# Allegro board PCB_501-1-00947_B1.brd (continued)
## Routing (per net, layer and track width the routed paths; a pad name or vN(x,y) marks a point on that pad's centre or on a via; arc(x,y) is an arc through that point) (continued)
SD2_DATA1: length 90.5
  TOP w0.137: v1(101.19,15.88) R179.1
  L3_INT_1 w0.127: v1(58.03,71.01) 58,70.99 57.31,70.99 57.12,70.79 57.12,69.69 57.37,69.44 57.61,69.44 57.82,69.23 57.82,60.83 63.37,55.28 63.37,54.86 79.98,38.25 79.98,24.24 88.35,15.88 89.6,15.88 89.79,15.69 89.79,15.5 89.97,15.32 90.24,15.32 90.42,15.5 90.42,15.79 90.58,15.95 90.84,15.95 91.06,15.74 91.06,15.5 91.24,15.32 91.51,15.32 91.69,15.5 91.69,15.79 91.85,15.95 92.11,15.95 92.33,15.74 92.33,15.5 92.51,15.32 92.78,15.32 92.96,15.5 92.96,15.79 93.12,15.95 93.38,15.95 93.6,15.74 93.6,15.5 93.78,15.32 94.05,15.32 94.23,15.5 94.23,15.79 94.39,15.95 94.65,15.95 94.87,15.74 94.87,15.5 95.05,15.32 95.32,15.32 95.5,15.5 95.5,15.79 95.66,15.95 95.92,15.95 96.14,15.74 96.14,15.5 96.32,15.32 96.59,15.32 96.77,15.5 96.77,15.79 96.93,15.95 97.19,15.95 97.41,15.74 97.41,15.5 97.59,15.32 97.86,15.32 98.12,15.58 98.53,15.58 98.8,15.32 99.13,15.32 99.31,15.5 99.31,15.69 99.5,15.88 99.76,15.88 99.95,15.69 99.95,15.5 100.13,15.32 100.4,15.32 100.58,15.5 100.58,15.69 100.77,15.88 v1(101.19,15.88)
  BOTTOM w0.137: R289.1 58.04,71.01 v1(58.03,71.01) ; R179.1 v1(101.19,15.88)
SD2_DATA2: length 88
  TOP w0.137: v1(101.19,14.73) R180.1
  L3_INT_1 w0.127: v1(57.2,68.8) 57.2,60.62 62.78,55.04 62.78,54.45 78.96,38.27 78.96,24.25 88.48,14.73 89.52,14.73 89.71,14.55 89.71,14.36 89.89,14.17 90.16,14.17 90.34,14.36 90.34,14.55 90.53,14.73 90.79,14.73 90.98,14.55 90.98,14.36 91.16,14.17 91.43,14.17 91.61,14.36 91.61,14.55 91.8,14.73 92.06,14.73 92.25,14.55 92.25,14.36 92.43,14.17 92.7,14.17 92.88,14.36 92.88,14.55 93.07,14.73 93.33,14.73 93.52,14.55 93.52,14.36 93.7,14.17 93.97,14.17 94.15,14.36 94.15,14.53 94.3,14.68 101.14,14.68 v1(101.19,14.73)
  BOTTOM w0.137: v1(57.2,68.8) 58.01,67.99 58.37,67.99 R290.1 ; R180.1 v1(101.19,14.73)
SD2_DATA3: length 95.5
  TOP w0.137: v1(101.19,13.59) R181.1
  L3_INT_1 w0.127: v1(101.19,13.59) 100.99,13.78 97.04,13.78 96.81,13.55 88.56,13.55 77.94,24.17 77.94,38.22 56.39,59.78 56.39,62.81 56.2,63 54.29,63 54.11,63.18 54.11,63.45 54.29,63.63 56.2,63.63 56.39,63.82 56.39,64.08 56.2,64.27 54.29,64.27 54.11,64.45 54.11,64.72 54.29,64.9 56.2,64.9 56.39,65.09 56.39,71.94 v1(56.69,72.24)
  BOTTOM w0.137: R291.1 56.69,72.71 v1(56.69,72.24) ; R181.1 v1(101.19,13.59)
SD3_CLK: length 8
  TOP w0.137: R125.1 65.72,63.73 65.72,69.93 R444.1
SD3_CLK_R: length 10.4
  TOP w0.076: 69.5,57.08 69.73,57.31 69.73,57.54 69.59,57.68 69.59,57.88 69.73,58.02 69.73,58.23 69.49,58.48 U10.M6
  TOP w0.137: 69.5,57.08 69.1,56.68 68.6,56.68 64.01,61.26 R125.2
SD3_CMD: length 15.3
  TOP w0.076: 67,62.39 69.51,59.88 69.51,59.57 U10.M5
  TOP w0.137: R445.1 67.34,71.46 67.8,71 67.8,70.15 66.18,68.53 66.18,68.28 R94.2 ; 66.45,68.01 R94.2 ; R94.2 66.45,62.94 67,62.39
SD3_DATA0: length 14.5
  TOP w0.076: 72.51,64.3 72.51,63.98 U10.A3
  TOP w0.137: v1(64.53,68.17) 64.53,68.57 R436.1 ; v1(71.7,65.54) 71.46,65.54 71.16,65.84 71.16,66.14 71.44,66.42 71.67,66.42 72.33,65.76 72.33,65.56 72.19,65.41 72.19,64.97 72.51,64.64 72.51,64.3
  L3_INT_1 w0.127: v1(64.53,68.17) 64.53,67.89 67.31,65.11 71.28,65.11 v1(71.7,65.54)
SD3_DATA1: length 13.4
  TOP w0.076: 72.81,64.3 72.81,63.58 72.67,63.44
  TOP w0.137: 72.81,64.3 72.81,65.05 v1(72.64,65.23) ; R437.1 64.03,67.78 v1(64.03,67.46)
  L3_INT_1 w0.127: v1(64.03,67.46) 66.95,64.53 67.06,64.53 67.06,64.53 71.52,64.53 71.52,64.53 72.51,64.53 72.64,64.66 v1(72.64,65.23)
SD3_DATA2: length 17
  TOP w0.076: U10.A5 73.44,63.5 73.44,63.68
  TOP w0.137: 73.44,63.68 73.44,64.81 74.12,65.49 74.12,67.13 73.92,67.32 73.73,67.32 73.4,66.99 73.21,66.99 73.01,67.19 73.01,67.38 73.37,67.73 73.37,67.93 73.17,68.12 71.54,68.12 71.21,67.79 v1(70.91,67.79) ; v1(69.73,73.37) 69.73,73.61 69.29,74.05
  L3_INT_1 w0.127: v1(69.73,73.37) 71.62,71.48 71.62,68.51 70.91,67.79 v1(70.91,67.79)
SD3_DATA3: length 16.2
  TOP w0.076: 70.7,65.05 70.45,65.05
  TOP w0.081: U10.B2 71.61,64.14 70.7,65.05
  TOP w0.137: R438.1 68.99,73.1 v1(68.99,72.68) ; v1(70.15,67.92) 70.15,67.92 70.15,67.21 69.59,66.65 69.59,66.34 69.72,66.22 70.02,66.22 70.17,66.07 70.17,65.79 70.02,65.63 69.46,65.63 69.11,65.98 68.92,65.98 68.65,65.71 68.65,64.54 68.85,64.34 69.18,64.34 69.33,64.49 69.33,64.87 69.51,65.05 70.45,65.05
  L3_INT_1 w0.127: v1(70.15,67.92) 70.15,70.29 70.13,70.3 70.13,71.54 v1(68.99,72.68)
SD3_DATA4: length 16.7
  TOP w0.081: 70.5,64.54 71.61,63.44 U10.B3
  TOP w0.137: v1(69.64,67.46) 68.24,66.07 68.24,63.88 68.42,63.7 68.78,63.7 68.97,63.51 68.97,63.16 69.16,62.97 69.44,62.97 69.91,63.44 69.91,63.61 69.6,63.92 69.6,64.15 69.99,64.54 70.5,64.54 ; v1(68.39,71.99) 68.39,72.39 R440.1
  L3_INT_1 w0.127: v1(69.64,67.46) 69.11,67.46 68.39,68.19 v1(68.39,71.99)
SD3_DATA5: length 18.3
  TOP w0.076: U10.B4 72.32,63.44
  TOP w0.081: 72.23,64.34 72.23,64.05 72.05,63.87 72.05,63.71 72.32,63.44
  TOP w0.137: v1(67,70.67) 67,71.17 R441.1 ; v1(70.62,67.17) 70.62,65.69 71.25,65.06 71.51,65.06 72.23,64.34
  L3_INT_1 w0.127: v1(67,70.67) 66.57,71.09 66.16,71.09 65.8,70.74 65.42,70.74 65.19,70.97 65.19,71.27 66,72.08 66.6,72.08 67.43,71.24 67.43,68.27 68.83,66.88 70.33,66.88 v1(70.62,67.17)
SD3_DATA6: length 16.3
  TOP w0.076: 73.12,63.54 73.12,63.89
  TOP w0.081: 73.12,63.54 72.67,63.08 U10.B5
  TOP w0.137: 73.12,63.89 73.12,65.38 73.63,65.89 73.63,66.17 73.4,66.4 73.12,66.4 72.89,66.17 72.64,66.17 72.28,66.52 72.28,67.39 72.1,67.56 71.7,67.56 v1(71.29,67.16) ; R443.1 66.72,70.18 v1(66.72,69.72)
  L3_INT_1 w0.127: v1(71.29,67.16) 71.2,67.07 71.2,66.93 70.57,66.3 68.58,66.3 66.76,68.12 66.76,69.68 v1(66.72,69.72)
SD3_DATA7: length 18.9
  TOP w0.076: 73.66,63.37 73.7,63.41
  TOP w0.081: 73.66,63.37 73.02,62.73 U10.B6
  TOP w0.127: 73.7,63.41 73.79,63.49
  TOP w0.137: 73.79,63.49 73.79,64.37 v1(73.95,64.54) ; R442.1 65.18,69.21 v1(65.18,68.33)
  L3_INT_1 w0.127: v1(73.95,64.54) 73.95,65.69 73.4,66.25 71.52,66.25 70.97,65.7 68.35,65.7 66.13,67.91 66.13,69.07 65.26,69.94 65.08,69.94 64.67,69.53 64.67,68.83 v1(65.18,68.33)
SD3_RESET_B: length 17.2
  TOP w0.076: U10.K5 69.84,60.76 69.8,60.8 69.8,61 67.71,63.09
  TOP w0.137: R446.1 70.19,74.43 70.19,72.61 68.2,70.62 R93.2 68.2,67.3 67.23,66.32 67.23,63.58 67.71,63.09
SD3_STROBE: length 9
  TOP w0.137: v1(68.95,68.26) 68.93,68.28 68.93,68.35 68.56,68.72 68.56,70.14 70.56,72.14 R447.1
  BOTTOM w0.137: R124.1 68.81,67.41 68.95,67.55 v1(68.95,68.26)
SD3_STROBE_R: length 9.7
  TOP w0.137: v1(70.2,60.96) 70.55,60.61 U10.H5
  BOTTOM w0.137: R124.2 66.85,64.49 66.85,62.62 68.52,60.95 R691.2 69.82,60.58 v1(70.2,60.96)
SD_PWR_CTRL: length 4.7
  BOTTOM w0.254: C194.2 92.47,54.25 R107.1
  BOTTOM w0.381: R107.1 93.67,54.2 Q6.1 93.67,55.04 R105.2
SD_PWR_DISCH: length 4.2
  BOTTOM w0.254: Q7.1 96.33,57.92 R104.2 96.99,56.64 98.26,55.37 D4.2
SOC_OTG2_DN: length 8.1
  TOP w0.127: 53.8,73.26 53.45,73.26 53.34,73.15 53.15,73.15 53.03,73.28 53.03,73.45 54.85,75.28 R559.1 55.82,75.53 55.82,75.79 55.38,76.23 55.38,77.68 56.05,78.34 U7.A10
SOC_OTG2_DP: length 8.8
  TOP w0.127: U7.B10 56.19,78.87 55.11,77.79 55.11,76.32 54.99,76.19 R558.1 54.55,75.36 52.75,73.57 52.75,73.04 52.9,72.89 R565.1
SOC_SD1_CLK: length 4.9
  TOP w0.137: R49.2 57.7,72.82 57.7,74.88 58.4,75.57 58.4,75.74 58.88,76.22 U7.B5
SOC_SD1_CMD: length 11
  TOP w0.137: R39.2 60.62,68.5 60.62,71.2 58.44,73.38 58.44,74.73 59.93,76.23 U7.C5
SOC_SD1_DATA0: length 10.2
  TOP w0.137: U7.A5 58.87,75.59 58.06,74.77 58.06,73.24 60.21,71.08 60.21,67.5 R41.2
SOC_SD1_DATA1: length 8.1
  TOP w0.102: v2(59.93,77.28) 59.93,77.28 U7.D6
  BOTTOM w0.137: R42.2 56.23,72.02 56.23,73.05 58.11,74.93 58.56,74.93 59.52,75.88 59.52,76.18 59.85,76.51 59.85,77.19 v2(59.93,77.28)
SOC_SD1_DATA2: length 8.5
  TOP w0.127: 59.4,75.15 U7.A4
  TOP w0.137: R43.2 61.07,69.32 61.07,71.18 58.79,73.46 58.79,74.54 59.4,75.15
SOC_SD1_DATA3: length 7.9
  TOP w0.102: U7.D5 v2(60.46,76.75)
  BOTTOM w0.137: v2(60.46,76.75) 60.32,76.6 60.32,76.2 60.06,75.94 60.06,75.29 57.19,72.43 57.19,72.01 56.63,71.45 R44.2
SOC_SD2_CLK: length 6.3
  TOP w0.102: U7.E3 v2(62.06,76.22)
  BOTTOM w0.137: v2(62.06,76.22) 62.22,76.06 62.22,74.7 60.59,73.07 60.59,71.76 R286.2
SOC_SD2_CMD: length 7.6
  TOP w0.102: U7.F6 60.99,78.34 v2(61,78.34)
  BOTTOM w0.137: R287.2 59.14,72.96 60.87,74.7 60.87,75.81 60.62,76.06 60.62,76.37 60.83,76.58 60.83,76.58 60.84,76.59 60.84,76.9 60.62,77.12 60.62,77.43 61,77.81 v2(61,78.34)
SOC_SD2_DATA0: length 9.2
  TOP w0.102: U7.E4 v2(61.53,76.75)
  BOTTOM w0.137: v2(61.53,76.75) 61.63,76.64 61.63,74.58 60.2,73.15 60.2,72.36 58.06,70.21 57.41,70.21
SOC_SD2_DATA1: length 6.6
  TOP w0.102: v2(61,77.28) 60.99,77.28 U7.E5
  BOTTOM w0.137: R289.2 59.29,72.66 61.37,74.74 61.37,76.37 61.17,76.57 61.17,76.58 61.15,76.59 61.15,77.12 v2(61,77.28)
SOC_SD2_DATA2: length 8.7
  TOP w0.102: v2(61.53,77.81) 61.53,77.81 U7.F5
  BOTTOM w0.137: R290.2 60.98,71.71 61.69,72.42 61.69,73.33 62.46,74.1 62.46,76.35 62.21,76.59 61.53,77.28 v2(61.53,77.81)
SOC_SD2_DATA3: length 5.8
  TOP w0.102: v2(60.46,77.81) 60.46,77.81 U7.E6
  BOTTOM w0.102: 59.79,75.56 59.79,76.07 60.07,76.35 60.07,76.87 60.32,77.12 60.32,77.67 v2(60.46,77.81)
  BOTTOM w0.127: R291.2 57.8,73.82
  BOTTOM w0.137: 57.8,73.82 58.32,74.35 58.58,74.35 59.79,75.56
SPI3_MISO: length 6
  BOTTOM w0.137: J14.40 9.15,36.33 9.31,36.49 9.33,36.49 9.46,36.62 10.23,36.62 11.09,37.48 11.09,38.92 R358.1
SPI3_MOSI: length 5.5
  BOTTOM w0.137: J14.39 9.13,35.83 9.5,36.21 10.24,36.21 11.4,37.37 11.4,38.29 R357.1
SPI3_SCLK: length 5.2
  BOTTOM w0.137: J14.38 9.17,35.33 9.68,35.84 10.78,35.84 11.9,36.96 11.9,37.82 R356.1
SPI_SS_B: length 35.3
  TOP w0.137: H4.3 4.67,58.04 6.95,55.75 11.4,55.75 14.19,52.96 14.19,51.84 15.12,50.92 v1(15.12,50.86)
  BOTTOM w0.137: J14.41 9.12,36.83 9.33,37.04 10.14,37.04 10.8,37.7 10.8,39.04 10.8,39.04 10.8,39.48 11.62,40.3 13.16,40.3 13.78,40.92 13.78,43.43 12.81,44.41 12.81,47.46 15.12,49.77 v1(15.12,50.86)
SPKLN: length 3.3
  TOP w0.254: H3.2 99.38,32.53 D28.2 99.37,34.77 FB17.2
SPKLP: length 5.4
  TOP w0.254: FB14.2 102.09,32.91 D27.2 102.04,29.05 H3.1
SPKOUTLN: length 1.8
  TOP w0.254: FB17.1 97.79,34.83 97.79,36.53 U24.23
SPKOUTLP: length 4.2
  TOP w0.254: FB14.1 100.17,35.16 100.17,35.81 99.06,36.93 U24.25
SPKOUTRN: length 1.5
  TOP w0.254: U24.19 95.79,36.01 95.67,35.89 95.67,35.13 FB16.1
SPKOUTRP: length 1.8
  TOP w0.254: U24.22 97.31,36.51 97.31,35.5 96.9,35.08 FB13.1
SPKRN: length 3.5
  TOP w0.254: H3.4 94.18,34.22 D30.2 94.9,34.51 95.11,34.3 FB16.2
SPKRP: length 5.6
  TOP w0.254: H3.3 96.83,28.93 D29.2 96.83,34.21 FB13.2
ST_CANH: length 3.6
  TOP w0.254: R245.1 R246.1 73.63,16.92 C506.1
ST_CLK_32K: length 2
  TOP w0.137: M1.36 119.93,13.84 R706.2
ST_ENET_MDC: length 9.4
  TOP w0.137: R95.2 74.17,74.74 73.42,75.49 73.42,76.38 71.54,78.26 71.54,78.73 70.76,79.51 70.76,79.86 69.09,81.52 U7.T1
ST_JTAG_TRS: length 12.6
  TOP w0.127: v1(112.87,104.39) 113.25,104.39 114.14,105.28 H2.10
  BOTTOM w0.127: D26.1 116.3,97.41 114.65,99.06 114.65,103.25 114.29,103.61 R168.1 R172.2 112.49,104.01 v1(112.87,104.39)
ST_LCD_CLK: length 105.7
  TOP w0.102: U7.E20 v2(53.57,85.77)
  L3_INT_1 w0.102: v2(53.57,85.77) 53.71,85.9 54.21,85.9 54.46,86.15 54.46,86.44 54.28,86.62 54.28,88.03 54.46,88.21 54.46,88.62 52.8,90.28 49.36,90.28
  L3_INT_1 w0.127: 49.36,90.28 42.31,90.28 40.03,88 40.03,82.84 38.99,81.79 36.74,81.79 33.04,78.09 33.04,77.91 33.54,77.41 33.54,77.23 33.36,77.05 33.18,77.05 32.68,77.55 32.5,77.55 32.32,77.37 32.32,77.19 32.85,76.67 32.85,76.49 32.67,76.31 32.49,76.31 31.96,76.83 31.78,76.83 28.92,73.97 28.92,73.79 29.91,72.8 29.91,72.62 29.73,72.44 29.55,72.44 28.56,73.43 28.38,73.43 28.2,73.25 28.2,73.07 29.23,72.04 29.23,71.86 29.05,71.68 28.87,71.68 27.84,72.71 27.66,72.71 24.41,69.47 24.41,52.05 24.98,51.48 v1(24.98,50.38)
  BOTTOM w0.137: v1(24.98,50.38) 24.98,49.71 27.27,47.42 27.27,38.61 21.56,32.89 R109.2
ST_MIC_N: length 3.2
  TOP w0.254: C260.2 93.11,43.41 R660.2 92.44,42.8 R684.1
ST_PHY_XO: length 1
  TOP w0.137: U13.14 39.58,32.29 R130.1
SUPER_CT: length 1.5
  TOP w0.381: U37.4 92.27,91.99 92.27,90.68 C393.1
SUPER_MR_B: length 7.1
  TOP w0.381: R127.1 89.25,90.65 89.25,88.17 D22.2 ; R127.1 86.42,90.68 D21.2 ; R127.1 89.27,90.68 89.27,91.99 U37.3
SUPER_RST_B: length 2.5
  TOP w0.127: R736.2 R350.2 89.27,94.19 U37.1
SUPER_SENSE: length 5.4
  TOP w0.381: U37.5 93.34,93.09 R348.1 C401.1 95.15,91.8 D16.2
SW_BT_MODE0: length 2.6
  TOP w0.127: R295.1 SW3.1
SW_BT_MODE1: length 2.6
  TOP w0.127: R296.1 SW3.2
SW_MX7_RST_B: length 11.8
  TOP w0.254: SW8.3 SW8.4 86.87,79.43 R347.2
SW_USR_BT0: length 13.1
  TOP w0.127: SW5.4 SW5.3 97.63,56.43 97.63,58.74 C578.1 97.62,60.36 R309.2
SW_USR_BT1: length 13.4
  TOP w0.127: SW7.4 SW7.3 117.14,56.36 C579.1 R310.2
TEMP_SENSOR_REXT: length 4.9
  TOP w0.127: U7.AE4 72.24,88 75.39,88 75.85,87.54 76.79,87.54
TEST_MODE: length 3.6
  TOP w0.102: v2(65.77,83.11) 65.77,83.11 U7.P6
  BOTTOM w0.102: R35.1 68,81.42 66.31,83.11 v2(65.77,83.11)
TMPSEN_RESERV: length 5.1
  TOP w0.127: R76.2 75.89,88.31 72.03,88.31 71.56,87.83 71.56,87.4 U7.AD4 71.6,87.36
TOUCH_X1: length 14.4
  BOTTOM w0.127: R590.2 19.52,40.21 13.15,33.84 9.52,33.84 9.01,33.33 J14.34
TOUCH_X1_C: length 5.3
  BOTTOM w0.127: U23.2 19.28,44.67 C420.2 20.47,43.47 20.47,42.4 19.58,41.5 R590.1
TOUCH_X2: length 12
  BOTTOM w0.127: J14.35 9.11,33.83 9.62,34.34 11.65,34.34 17.11,39.8 R592.2
TOUCH_X2_C: length 5.3
  BOTTOM w0.127: R592.1 17.56,41.95 17.56,43.5 C422.2 17.98,45.06 U23.4
TOUCH_Y1: length 12.9
  TOP w0.127: v1(15.46,37.08) 12.5,37.08 v1(10.25,34.84)
  BOTTOM w0.127: J14.36 9.1,34.33 9.61,34.84 v1(10.25,34.84) ; v1(15.46,37.08) 18.28,39.9 R591.2
TOUCH_Y1_C: length 4.9
  BOTTOM w0.127: U23.3 18.63,44.16 C421.2 17.86,43.4 17.86,41.92 R591.1
TOUCH_Y2: length 10.7
  BOTTOM w0.127: J14.37 9.19,34.83 9.7,35.34 11.93,35.34 15.99,39.4 R593.2
TOUCH_Y2_C: length 5.6
  BOTTOM w0.127: R593.1 15.28,42.21 15.28,43.36 C423.2 17.33,45.4 U23.5
TP_BUSY: length 76.1
  TOP w0.127: v1(47.59,95.44) 47.65,95.44 R380.2
  L3_INT_1 w0.127: v1(47.59,95.44) 33.24,95.44 31.74,93.95 31.74,86.24 24.52,79.02 23.37,79.02 22.15,77.8 22.15,76.41 20.59,74.85 16.03,74.85 13.43,72.25 13.43,68.04 12.16,66.77 v1(12.16,56.02)
  BOTTOM w0.127: U23.13 17.98,52.55 18.27,52.84 18.27,53.99 15.91,56.34 12.49,56.34 12.18,56.02 v1(12.16,56.02)
TP_ESPI3_SS2_B: length 74.4
  TOP w0.102: U7.D3 61.53,75.68 61.13,75.28 61.13,75.04 62.06,74.1 62.06,73.25 v1(62.26,73.06)
  TOP w0.127: U33.2 13.56,58.55 14.83,57.27 14.83,54.29 14.84,54.28 14.84,53.91 14.83,53.91 14.83,51.98 v1(14.79,51.95)
  L6_INT_2 w0.127: v1(14.79,51.95) 14.9,52.06 24.45,52.06 24.84,51.66 44.91,51.66 52.47,59.23 52.47,61.11 53.99,62.63 53.99,69.07 54.79,69.86 54.79,71.17 56.9,73.28 62.04,73.28 v1(62.26,73.06)
TP_ESPI_SS_B: length 6.8
  TOP w0.127: U33.4 9.19,60.1 7.77,60.1 R656.2 4.67,62.08 H4.2
TP_INT_B: length 65
  TOP w0.127: v1(48.61,92.46) 48.71,92.36 51.22,92.36 53.57,90.01 54.1,90.01
  L3_INT_1 w0.127: v1(48.61,92.46) 48.56,92.51 42.02,92.51 36.2,86.68 36.2,82.73 20.96,67.5 20.96,61.02 v1(15.78,55.84)
  BOTTOM w0.127: U23.11 16.68,55.08 15.92,55.84 v1(15.78,55.84)
TP_OUT3: length 1.4
  BOTTOM w0.127: TP29.1 102.88,38.73 C276.2
TP_SPI_SS_B: length 21.7
  TOP w0.127: H4.1 9.36,64.77 19.27,54.86 v1(19.27,53.14)
  BOTTOM w0.127: U23.15 19.28,53.13 v1(19.27,53.14)
TPS51200_PG: length 3.4
  TOP w0.203: TP76.1 82.42,107.72 R715.2 82.38,109.25 U51.9
TPS51200_REFIN: length 5.9
  TOP w0.254: R716.1 R717.2 86.5,113.81 C534.1 85.29,113.64 84.93,114 U51.1
TX_LED1: length 21.1
  TOP w0.254: D9.1 v1(124.28,119.25)
  L3_INT_1 w0.254: v1(107.05,116.1) 107.26,116.31 107.26,116.31 107.55,116.61 107.57,116.61 107.67,116.71 121.74,116.71 v1(124.28,119.25)
  BOTTOM w0.254: v1(107.05,116.1) 106.98,116.18 U18.11
TX_LED2: length 23.3
  TOP w0.254: v1(121.76,114.43) D11.1
  L3_INT_1 w0.254: v1(121.76,114.43) v1(117.06,109.73)
  BOTTOM w0.254: U18.27 106.48,107.59 107.13,106.93 114.27,106.93 v1(117.06,109.73)
UART1_RXD: length 70.9
  TOP w0.127: U7.L3 v2(65.24,79.4)
  L3_INT_1 w0.102: v2(65.24,79.4) 65.49,79.15 67.45,79.15 69.02,77.58 69.54,77.58
  L3_INT_1 w0.127: 69.54,77.58 72.62,77.58 73.33,78.29 80.54,78.29 80.94,78.68 81.29,78.68 81.59,78.99 81.59,79.34 81.71,79.45 82.41,79.45 85.44,82.48 85.44,83.19 94.37,92.12 104.55,92.12 110.84,98.4 110.84,103.12 112.74,105.03 112.74,110.29 v1(112.44,110.59)
  BOTTOM w0.137: U17.6 v1(112.44,110.59)
UART1_TXD: length 73
  TOP w0.102: U7.L4 v2(64.71,79.93)
  L3_INT_1 w0.102: 69.26,77.3 68.84,77.3 68.68,77.46 67.66,77.46 66.26,78.86 65.28,78.86 64.71,79.43 v2(64.71,79.93)
  L3_INT_1 w0.127: 69.26,77.3 72.83,77.3 73.47,77.94 81.61,77.94 95.16,91.49 104.97,91.49 111.6,98.12 111.6,101.85 114.14,104.39 114.14,109.96 v1(113,111.1)
  BOTTOM w0.137: v1(113,111.1) 113,111.09 U17.5
UART2_RXD: length 55.2
  TOP w0.102: v2(64.18,80.46) 64.18,80.46 U7.L5
  L3_INT_1 w0.102: v2(64.18,80.46) 64.7,80.46 65.66,79.5 67.56,79.5 69.19,77.86 69.82,77.86
  L3_INT_1 w0.127: v1(102.6,104.75) 101.63,103.78 101.63,100.96 84.54,83.88 84.54,81.98 82.29,79.73 74.29,79.73 72.46,77.9 arc(72.42,77.87) 72.37,77.86 69.82,77.86
  BOTTOM w0.137: U19.6 v1(102.6,104.75)
UART2_TXD: length 53.7
  TOP w0.102: U7.L6 63.65,80.99 v2(63.65,80.99)
  L3_INT_1 w0.102: v2(63.65,80.99) 63.81,81.16 65.4,81.16 65.59,81.35 66.98,81.35 68.17,80.16 70.86,80.16
  L3_INT_1 w0.127: 70.86,80.16 81.91,80.16 83.13,81.39 83.13,83.93 101.28,102.08 101.28,104.39 v1(102.09,105.2)
  BOTTOM w0.137: v1(102.09,105.2) 102.1,105.21 U19.5
UART5_CTS: length 80.9
  TOP w0.102: v2(57.28,79.93) 57.28,79.93 U7.D11
  TOP w0.137: H5.3 59.91,126.24 56.86,123.19 50.95,123.19 47.82,120.06 47.82,108.37 v1(47.49,108.04)
  L6_INT_2 w0.102: v2(57.28,79.93) 57.79,79.93 58.17,80.31 58.17,81.16 57.46,81.87 57.46,82.73 57.63,82.9 57.63,83.29 54.27,86.65 53.9,86.65 53.72,86.47 53.43,86.47 53.24,86.65 52.9,86.65 52.71,86.47 52.36,86.47 52.18,86.65 51.83,86.65 51.65,86.47 51.3,86.47 50.77,87 46.79,87
  L6_INT_2 w0.127: 46.79,87 43.36,87 42.12,88.24 v1(42.12,88.31)
  BOTTOM w0.127: v1(42.12,88.31) 37.96,92.47 37.96,106.08 39.92,108.04 v1(47.49,108.04)
UART5_RTS: length 78.5
  TOP w0.102: v2(57.81,80.46) 57.81,80.46 U7.E11
  TOP w0.137: v1(47.23,108.94) 46.84,109.33 46.84,119.57 51.15,123.88 55.11,123.88 57.37,126.15 H5.2
  L6_INT_2 w0.102: 46.79,86.51 50.15,86.51 50.72,85.94 51.12,85.94 51.3,86.12 51.6,86.12 51.78,85.94 53.19,85.94 53.37,86.12 53.77,86.12 57.09,82.8 57.09,81.95 57.81,81.23 v2(57.81,80.46)
  L6_INT_2 w0.127: 46.79,86.51 42.02,86.51 v1(41.18,87.35)
  BOTTOM w0.127: v1(41.18,87.35) 41.18,88.85 37.68,92.35 37.68,92.35 37.11,92.93 37.11,106.28 39.77,108.94 v1(47.23,108.94)
UART5_RX: length 121.1
  TOP w0.137: H5.4 62.45,127.34 68.64,121.15 95.91,121.15 100.11,116.95 100.11,91.87 94.34,86.1 88.48,86.1 84.38,82 84.38,73.85 v1(82.8,72.26) ; v1(81.75,69.48) 81.38,69.11 81.15,69.11 81.15,69.1 78.17,69.1 78.17,69.11 78.02,69.11 72.19,74.94 72.19,75.81 70.58,77.42 67.23,77.42 66.63,78.02 66.63,78.54 U7.L1
  BOTTOM w0.137: v1(82.8,72.26) 82.8,70.53 v1(81.75,69.48)
UART5_TX: length 119.6
  TOP w0.137: U7.L2 66.3,79.4 66.88,78.82 66.88,78.28 67.39,77.78 70.77,77.78 72.48,76.07 72.48,75.94 72.48,75.93 72.48,75.06 78.14,69.4 81.03,69.4 84.67,73.04 84.67,81.88 88.6,85.81 94.48,85.81 100.63,91.97 100.63,117.21 96.37,121.47 71.03,121.47 H5.5
UART6_CTS_B: length 127.8
  TOP w0.102: U7.H5 v2(62.59,78.87)
  TOP w0.137: v1(116.68,26.92) 117.42,26.92 R755.2 ; v1(100.79,22.78) 84.5,22.78 69.12,38.16 69.12,45.27 80.87,57.02 82.64,57.02 v1(84.04,58.42) ; R756.2 121.15,25.7 v1(121.94,25.7) 121.94,24.33 TP53.1
  L3_INT_1 w0.102: v2(62.59,78.87) 63.13,78.87 64.22,77.78 64.71,77.78 65.71,76.78 65.71,76.59 66.32,75.99
  L3_INT_1 w0.127: 66.32,75.99 67.06,75.25 70.91,75.25 72.92,73.24 74.94,73.24 76.44,71.74 76.44,71.7 76.74,71.39 76.78,71.39 77.25,70.93 77.88,70.93 78.14,70.67 78.14,70.04 78.15,70.03 78.15,69.27 85.12,62.29 85.12,59.37 84.17,58.42 v1(84.04,58.42)
  L6_INT_2 w0.127: v1(121.94,25.7) 120.72,26.92 v1(116.68,26.92)
  BOTTOM w0.137: v1(100.79,22.78) 100.81,22.81 105.29,22.81 109.41,26.92 v1(116.68,26.92)
UART6_RTS_B: length 126.4
  TOP w0.102: U7.H4 63.12,78.34 v2(63.12,78.34)
  TOP w0.137: v1(100.79,23.57) 100.68,23.68 84.11,23.68 69.82,37.97 69.82,44.96 81.37,56.52 83.28,56.52 84.55,57.78 v1(84.55,59.44) ; v1(123.16,26.16) 122.7,26.62 R754.2 119.24,26.62 118.79,26.17 R757.2
  L3_INT_1 w0.102: 65.64,75.31 63.29,77.66 63.29,78.17 v2(63.12,78.34)
  L3_INT_1 w0.127: v1(84.55,59.44) 84.55,60.83 74.2,71.18 73.82,71.18 70.57,74.44 66.52,74.44 65.64,75.31
  BOTTOM w0.137: v1(100.79,23.57) 100.85,23.63 105.71,23.63 109.51,27.43 121.89,27.43 v1(123.16,26.16)
UART6_RXD: length 118.4
  TOP w0.102: v2(63.65,77.81) 63.65,77.81 U7.H3
  TOP w0.137: v1(116.04,25.91) 117.13,24.82 M1.52 ; v1(100.83,21.88) 100.83,21.88 84.77,21.88 68.42,38.22 68.42,45.49 80.59,57.66 81.88,57.66 84.68,60.45 v1(84.68,61.47)
  L3_INT_1 w0.102: v2(63.65,77.81) 63.65,77.81 65.96,75.5
  L3_INT_1 w0.127: v1(84.68,61.47) 84.68,61.85 73.63,72.9 72.77,72.9 70.8,74.88 66.59,74.88 65.96,75.5
  BOTTOM w0.137: v1(100.83,21.88) 104.81,21.88 109.09,26.16 115.79,26.16 v1(116.04,25.91)
UART6_TXD: length 119.3
  TOP w0.102: U7.G5 v2(62.06,78.34)
  TOP w0.137: M1.53 116.43,24.63 116.09,24.97 115.45,24.97 114.9,25.53 v1(113.5,25.53) ; v1(83.77,60.82) 83.77,60.18 81.79,58.2 80.03,58.2 67.89,46.06 67.89,38.12 85.03,20.98 100.76,20.98 v1(100.84,21.06)
  L3_INT_1 w0.102: v2(62.06,78.34) 62.06,77.82 63.72,76.16
  L3_INT_1 w0.127: v1(83.77,60.82) 70.44,74.16 65.37,74.16 63.72,75.81 63.72,76.16
  BOTTOM w0.137: v1(113.5,25.53) 109.02,25.53 104.51,21.01 100.89,21.01 v1(100.84,21.06)
USB2ANY_I2C1_SCL: length 14.8
  TOP w0.137: R234.2 86.74,127.12 75.9,127.12 H1.1
USB2ANY_I2C1_SDA: length 14.7
  TOP w0.137: R238.1 86.79,121.85 75.86,121.85 H1.2
USB_DN: length 23
  TOP w0.127: v1(107.89,118.7) 108.17,118.98 108.77,118.98 108.96,118.79 108.96,118.6 109.23,118.34 109.42,118.34 109.68,118.08 109.68,117.89 109.95,117.62 110.14,117.62 110.4,117.36 110.4,117.17 110.66,116.9 110.85,116.9 119.82,107.94 120.89,107.94 R160.1
  BOTTOM w0.127: U18.8 105.48,118.1 105.32,118.26 105.32,118.7 105.45,118.83 106.27,118.83 106.4,118.96 107.5,118.96 107.76,118.7 v1(107.89,118.7)
USB_DP: length 23
  TOP w0.127: R158.1 121.2,108.21 119.93,108.21 108.89,119.26 108.17,119.26 v1(107.89,119.54)
  BOTTOM w0.127: v1(107.89,119.54) 107.58,119.23 105.97,119.23 R159.1 105.7,119.1 105.33,119.1 105.05,118.82 105.05,118.25 104.98,118.18 U18.7
USB_HOST_N: length 6.9
  TOP w0.127: J26.2 43.26,15.96 46.83,15.96 P11.2 47.37,15.99 48.31,15.99 FL2.3
USB_HOST_P: length 6.9
  TOP w0.127: 47.08,16.55 46.77,16.24 43.22,16.24 J26.3 ; 47.08,16.55 P8.2 47.08,16.55 ; 47.08,16.55 47.37,16.26 48.29,16.26 48.55,16.53 FL2.2
USB_HOST_VBUS: length 71.6
  L3_INT_1 w0.406: 51.89,72.78 51.89,75.46 v1(53.35,76.92)
  L3_INT_1 w0.508: v1(60.8,15.62) 61.3,16.12 61.3,24.64 49.8,36.14 49.8,65.79 50.69,66.69 50.69,71.58 51.89,72.78
  BOTTOM w0.305: v1(53.35,76.92) 53.35,76.51 R69.2
  BOTTOM w0.508: 43.45,12 J26.1 41.29,12
USB_OTG1_DN: length 71.9
  TOP w0.127: FL1.3 52.91,10.75 53.17,11.02 53.17,44.57 53.04,44.71 53.04,45.08 53.17,45.22 53.17,45.59 53.04,45.72 53.04,46.1 53.17,46.23 53.17,46.61 53.04,46.74 53.04,47.11 53.17,47.25 53.17,47.61 55.67,50.11 55.67,50.3 55.93,50.57 56.13,50.57 56.39,50.83 56.39,51.02 56.65,51.28 56.84,51.28 57.11,51.55 57.11,51.74 57.37,52 57.56,52 57.78,52.22 57.78,70.13 55.97,71.94 55.97,71.96 55.02,72.9 55.02,73.59 56.41,74.98 56.41,76.23 57.28,77.11 U7.A8
USB_OTG1_DP: length 71.8
  TOP w0.127: U7.B8 57.64,77.64 57.64,77.08 56.68,76.12 56.68,74.86 55.3,73.48 55.3,73.02 56.24,72.07 56.24,72.05 58.05,70.24 58.05,52.11 53.44,47.5 53.44,11.02 53.71,10.75 FL1.2
USB_OTG1_ID: length 76.3
  TOP w0.127: U7.B7 58.34,76.76 57.4,75.82 57.4,72.36 59.41,70.35 59.41,51.95 55.38,47.92 P5.2 54.6,5.45 54.6,5.44 54.33,5.17 54.33,4.3 J25.4
USB_OTG1_OC: length 88.4
  TOP w0.102: U7.N6 v2(64.71,82.05)
  BOTTOM w0.102: 69.18,77.22 68.18,78.22 68.18,78.38 66.79,79.78 66.79,80.47 65.21,82.05 v2(64.71,82.05)
  BOTTOM w0.127: 69.18,77.22 72.48,73.91 72.48,68.22 75.39,65.32 75.39,35.68 72.25,32.54 62.05,32.54 53.57,24.06 53.57,18.4 53.66,18.31 R257.1 55.75,18.31 57.12,19.68 U30.2
USB_OTG1_PWR: length 80.1
  TOP w0.102: U7.P1 67.89,80.41 68.7,79.6 68.7,79.12 v1(68.72,79.1)
  BOTTOM w0.102: 69.44,77.48 68.72,78.19 v1(68.72,79.1)
  BOTTOM w0.127: U30.1 R126.2 R253.1 54.32,22.38 54.21,22.49 54.21,24.3 61.84,31.93 72.03,31.93 75.67,35.56 75.67,65.57 72.81,68.43 72.81,74.1 69.44,77.48
USB_OTG2_DN: length 60.9
  TOP w0.127: R566.2 54.48,71.92 56.73,69.68 56.73,53.71 51.87,48.85 51.87,48.54 52.01,48.4 52.01,48.03 51.87,47.89 51.87,47.52 52.01,47.38 52.01,47.01 51.87,46.87 51.87,46.5 52.01,46.37 52.01,46 51.87,45.86 51.87,16.41 51.45,15.99 51.1,15.99 50.83,15.73 FL2.4
USB_OTG2_DP: length 60.3
  TOP w0.127: FL2.1 50.81,16.53 51.07,16.26 51.34,16.26 51.6,16.52 51.6,48.96 56.46,53.82 56.46,54.09 56.32,54.22 56.32,54.6 56.46,54.73 56.46,55.11 56.32,55.24 56.32,55.61 56.46,55.75 56.46,56.12 56.32,56.25 56.32,56.63 56.46,56.76 56.46,69.56 54.29,71.73 53.62,71.73 R565.2
USB_OTG2_ID: length 6.3
  TOP w0.102: U7.B11 55.68,79.4 55.49,79.22
  TOP w0.127: R68.1 53.34,76.44 53.55,76.44 54.34,77.23 54.34,78.07 55.49,79.22
USB_OTG2_OC: length 81
  TOP w0.127: v2(66.81,81) 67.35,81 U7.P2
  BOTTOM w0.102: v2(66.81,81) 67.64,80.16 68.12,80.16 68.52,79.76 68.98,79.76 69.49,79.25 70.48,79.25 70.86,79.63
  BOTTOM w0.127: 70.86,79.63 71.92,79.63 72.62,78.93 73.18,78.93 76.1,76 76.1,71.18 76.59,70.7 76.59,35.19 71.69,30.29 63.94,30.29 57.86,24.22 57.86,23.02 R255.1 58.47,20.08 U30.3
USB_OTG2_PWR: length 83.8
  TOP w0.102: U7.P3 v2(67.31,81.52)
  BOTTOM w0.102: 69.81,80.21 69.71,80.11 68.47,80.11 68.06,80.52 67.96,80.52 67.31,81.17 v2(67.31,81.52)
  BOTTOM w0.127: 69.81,80.21 72.6,80.21 77.31,75.49 77.31,72.87 79.04,71.15 79.04,36.71 77.48,35.15 77.48,35.14 72.21,29.88 64.79,29.88 59.24,24.33 59.24,22.77 59.6,22.41 R252.1 59.77,22.38 R254.2 60.8,21.59 59.66,20.45 U30.4
USB_OTG_N: length 4.2
  TOP w0.127: J25.2 53.03,4.87 53.21,5.06 53.21,5.9 P6.2 53.17,6.51 53.17,7.64 52.91,7.9 FL1.4
USB_OTG_P: length 4.2
  TOP w0.127: J25.3 53.68,4.81 53.48,5.01 53.48,5.98 P7.2 53.44,6.51 53.44,7.64 53.71,7.9 FL1.1
USB_OTG_SHIELD: length 12.3
  TOP w0.508: R251.1 C252.1 48.78,2.24 49.57,1.45 J25.S1 50.13,1.45 51.35,2.67 56,2.67 57.23,1.45 J25.S2
USB_OTG_VBUS: length 72.6
  L3_INT_1 w0.406: v1(56.23,73.74) 56.2,73.76 55.53,73.76 55.14,73.37 55.14,69.99 52.33,67.19 52.33,63.69 51.68,63.04 51.68,39.05 62.4,28.32 62.4,16.36 61.05,15.01 56.84,15.01 v1(55.85,16)
  BOTTOM w0.406: v1(56.23,73.74) 56.46,73.97 R65.2
USB_PCIE_DN: length 94.2
  TOP w0.127: v1(54.46,74.09) 54.89,74.53 R559.2
  L6_INT_2 w0.127: v1(54.46,74.09) 54.21,74.34 53.83,74.34 53.54,74.05 53.54,73.87 54.1,73.31 54.59,73.31 56.27,75 61.91,75 65.41,71.49 88.12,71.49 89.25,70.36 v1(89.65,70.36)
  BOTTOM w0.127: FL3.3 100.06,88.51 99.58,88.99 99.58,89.42 99.78,89.62 99.78,89.93 99.58,90.13 99.58,90.38 100.22,91.02 100.51,91.02 100.64,90.89 101.02,90.89 101.15,91.02 102.52,91.02 102.72,90.82 102.72,90.64 102.98,90.37 103.17,90.37 103.44,90.1 103.44,89.92 103.7,89.65 103.89,89.65 104.15,89.39 104.15,89.2 104.42,88.93 104.61,88.93 104.87,88.67 104.87,88.48 105.14,88.21 105.32,88.21 110.27,83.27 110.27,83 110.14,82.87 110.14,82.49 110.27,82.36 110.27,81.98 110.14,81.85 110.14,81.47 110.27,81.34 110.27,80.96 110.14,80.83 110.14,80.46 110.27,80.33 110.27,79.95 110.14,79.82 110.14,79.44 110.27,79.31 110.27,70.76 109.36,69.85 109.12,69.85 108.88,69.61 108.88,69.37 108.64,69.13 108.4,69.13 108.16,68.89 108.16,68.65 107.98,68.47 94.09,68.47 93.96,68.61 93.59,68.61 93.45,68.47 93.08,68.47 92.94,68.61 92.57,68.61 92.43,68.47 92.06,68.47 91.93,68.61 91.55,68.61 91.42,68.47 91.13,68.47 89.65,69.96 v1(89.65,70.36)
USB_PCIE_DP: length 94.3
  TOP w0.127: v1(53.42,75.13) 53.49,75.13 R558.2 53.87,75.51
  L6_INT_2 w0.127: v1(53.42,75.13) 53.71,74.84 53.71,74.61 53.27,74.16 53.27,73.75 53.98,73.04 54.7,73.04 56.39,74.72 61.8,74.72 65.3,71.22 88.01,71.22 89.06,70.17 v1(89.06,69.77)
  BOTTOM w0.127: FL3.2 99.3,88.38 99.3,90.45 99.31,90.46 99.31,90.49 100.11,91.29 102.63,91.29 110.54,83.38 110.54,70.65 108.1,68.2 91.02,68.2 89.45,69.77 v1(89.06,69.77)
USB_SUSPEND1_B: length 14.9
  BOTTOM w0.127: U17.1 112.27,109.59 112.77,110.09 U17.7 114.76,110.09 115.14,110.47 115.14,114.57 114.08,115.63 U18.13
USB_SUSPEND2_B: length 11.4
  BOTTOM w0.127: U19.7 103.1,104.64 103.6,104.14 U19.1 103.92,102.74 105.54,102.74 106.04,103.23 106.04,106.63 105.48,107.19 U18.29
USR_BT0: length 46.3
  TOP w0.127: v1(96.61,59.54) 96.61,60.4 R309.1 ; U7.G3 v2(63.12,77.28)
  L3_INT_1 w0.102: 66,76.74 66,77.01 63.79,79.22 62.44,79.22 62.23,79.02 62.23,78.71 62.98,77.95 62.98,77.41 v2(63.12,77.28)
  L3_INT_1 w0.127: v1(96.61,59.54) 90.78,59.54 76.79,73.52 73.14,73.52 71.08,75.58 67.12,75.58 66,76.7 66,76.74
USR_BT1: length 67.5
  TOP w0.102: 60.09,73.2 60.09,74.29 60.85,75.05 60.85,75.54 U7.C3
  TOP w0.127: v1(61.6,71) 61.6,71.21 60.09,72.72 60.09,73.2 ; R310.1 112.71,59.64 111.3,58.23 100.25,58.23 v1(99.76,57.73)
  L3_INT_1 w0.127: v1(99.76,57.73) 98.79,56.77 84.14,56.77 77.45,63.46 66.9,63.46 62.61,67.74 62.61,69.99 v1(61.6,71)
VMIDC: length 2
  TOP w0.254: U24.27 99.67,38.29 99.93,38.03 C273.1
VSNVS: length 214.8
  TOP w0.305: U7.AD8 69.48,89.98 v2(69.48,89.98)
  TOP w0.381: R249.2 94.17,68.81 89.99,72.99 89.99,81.39 92.29,83.69 96.18,83.69 96.19,83.69 96.62,83.69 99,86.07 v1(99,87.22) ; R127.2 90.24,91.58 90.98,92.32 90.98,95.71 91.53,96.27 94.68,96.27 94.93,96.01 94.93,96.01 95.47,96.01 95.98,95.5 D16.1
  TOP w0.508: R348.2 93.35,94.04 92.27,94.04
  L3_INT_1 w0.508: v1(20.29,80.42) 23.59,80.42 30.83,87.65 30.83,94.95 33.34,97.46 44.94,97.46 46.83,99.37 46.83,100.09 46.27,100.65 46.27,113.23 49.12,116.08 49.12,116.12 49.48,116.48 51.68,116.48 56.98,121.78 61.87,121.78 62.86,120.79 62.9,120.79 63.26,120.43 63.26,120.4 67.48,116.18 67.48,116.17 69.94,113.71 69.94,110.49 71.4,109.04 73.45,109.04 73.78,108.7 75.03,108.7 77.03,106.7 77.03,106.18 78.07,105.14 78.07,97.04 71.48,90.45 70.68,90.45 70.22,89.98 v2(69.48,89.98)
  L6_INT_2 w0.508: 97.19,95.33 95.17,95.33 94.53,94.69 89,94.69 82.96,88.65 v1(78.93,88.65) ; 97.19,95.33 99.28,93.23 99.28,87.5 v1(99,87.22) ; 97.19,95.33 v1(97.19,95.33)
  BOTTOM w0.127: R687.2 18.6,79.5 18.6,73.48 18.1,72.97 17.33,72.97 15.05,75.26 R763.2
  BOTTOM w0.406: D34.1 73.88,89.66 72.01,89.66 71.25,90.42 70.68,90.42 70.03,89.77 C94.1 69.81,89.66 v2(69.48,89.98)
  BOTTOM w0.508: R687.2 v1(20.29,80.42) ; v1(78.93,88.65) 77.15,90.43 74.98,90.43 D34.1
WL_DBG: length 6.5
  TOP w0.127: TP54.1 125.19,18.16 121,18.16 120.81,17.97 M1.42
WL_IRQ: length 109
  TOP w0.102: v2(62.06,79.4) U7.H6
  TOP w0.127: M1.14 106.29,13.77 105.22,12.71 R682.1 105.22,11.98 105.1,11.86 104.64,11.86 104.6,11.82 103.92,11.82 103.88,11.86 100.78,11.86 100.6,12.04 93.34,12.04 67.28,38.1 67.28,46.74 78.33,57.78 v1(78.33,63.63)
  L3_INT_1 w0.102: 64.58,74.25 61.17,77.66 61.17,77.96 62.03,78.81 62.03,79.37 v2(62.06,79.4)
  L3_INT_1 w0.127: v1(78.33,63.63) 78.33,65.41 69.92,73.82 65.01,73.82 64.58,74.25
WL_REG_ON: length 109.7
  TOP w0.102: v2(61.53,78.87) U7.G6 61.52,79.4
  TOP w0.127: M1.40 v1(120.94,16.57)
  L3_INT_1 w0.102: 58.73,72.89 58.73,76.58 61.01,78.87 v2(61.53,78.87)
  L3_INT_1 w0.127: v1(101.1,18.95) 101.1,19.97 100.09,20.98 90.67,20.98 84.29,27.36 84.29,42.87 74.53,52.63 69.93,52.63 60.14,62.42 60.14,70.65 58.73,72.06 58.73,72.89
  L6_INT_2 w0.127: v1(101.1,18.95) 101.11,18.94 103.92,18.94 105.07,17.79 119.85,17.79 120.94,16.71 v1(120.94,16.57)
WL_RX: length 16.5
  TOP w0.137: v1(114.33,10.02) M1.26
  L6_INT_2 w0.127: v1(103.85,4.06) 103.85,7.67 106.79,10.61 113.75,10.61 v1(114.33,10.02)
WL_SDIO_CLK: length 5.1
  TOP w0.137: R176.2 103.36,18.71 104.7,18.71 105.22,18.19 C224.1 105.41,17.97 M1.8
WL_SDIO_CMD: length 5.1
  TOP w0.137: M1.6 105.28,19.37 C223.1 105.22,19.46 104.71,19.97 103.35,19.97 R177.2
WL_SDIO_D0: length 5.2
  TOP w0.137: M1.10 105.67,16.57 C222.1 104.71,17.53 103.32,17.53 R178.2
WL_SDIO_D1: length 5
  TOP w0.137: M1.11 105.23,15.87 C221.1 105.22,15.9 104.73,16.4 103.33,16.4 R179.2
WL_SDIO_D2: length 5.3
  TOP w0.137: R180.2 103.4,15.32 104.63,15.32 C220.1 105.66,15.17 M1.12
WL_SDIO_D3: length 5.4
  TOP w0.137: R181.2 103.33,14.11 104.73,14.11 105.22,13.61 C219.1 106.11,14.47 M1.13
WL_TX: length 15.5
  TOP w0.137: v1(115.03,10.02) M1.27
  L6_INT_2 w0.127: v1(105.38,4.06) 105.38,8.12 106.79,9.54 114.55,9.54 v1(115.03,10.02)
WL_UART6_CTS: length 2
  TOP w0.137: M1.51 117.83,25.54 R757.1
WL_UART6_RTS: length 2.8
  TOP w0.127: M1.50 118.53,24.05 R756.1
XTALI: length 11.3
  TOP w0.137: X2.1 76.8,76.28 76.8,77.84 75.99,78.65 75.44,78.65 75.27,78.48 C105.1 73.7,78.81 73.7,80.18 72.27,81.61 71.12,81.61 70.15,82.58 U7.V1
XTALO: length 5.3
  TOP w0.137: R284.1 R38.1 73.13,81.96 71.17,81.96 70.01,83.11 U7.V2
XTC_XO: length 3.2
  TOP w0.137: X2.3 76.1,80.18 C106.1 76.02,80.59 74.66,80.59

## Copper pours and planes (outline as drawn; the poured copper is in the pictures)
5VIN on TOP: 34.76,114.68 34.76,121.16 35.02,121.41 42.89,121.41 43.65,120.65 43.65,112.52 41.5,110.36 41.5,108.58 41.24,108.33 40.61,108.33 38.64,106.36 36.86,106.36 35.53,105.03 32.22,105.03 32.22,105.03 30.65,105.03 30,105.68 30,106.1 29.72,106.39 29.54,106.39 29.42,106.5 29.42,110.34 29.7,110.62 30.7,110.62
GND on BOTTOM (solid shape): 62.83,92.9 62.83,91.82 63.16,91.49 63.42,91.49 64.1,92.18 64.2,92.18 64.28,92.1 64.28,91.28 64.9,90.66 64.9,90.47 64.66,90.24 64.66,90.04 64.78,89.93 64.76,89.92 64.76,89.79 64.3,89.33 64.1,89.33 63.95,89.48 63.94,89.5 63.77,89.75 63.46,89.73 62.7,89.73 61.1,91.33 60.99,91.33 60.79,91.53 60.65,91.53 60.36,91.24 60.36,91.19 60.34,91.15 60.31,91.14 59.89,91.14 59.72,91.31 59.45,91.31 59.02,90.88 58.69,90.88 58.18,91.39 58.16,91.42 58.15,91.43 58.15,91.45 58.15,91.71 58.3,91.87 58.41,91.87 58.62,91.67 59.02,91.67 60.7,93.34 60.9,93.34 61.38,92.86 61.82,92.86 62.32,93.37 62.37,93.37
GND on TOP: 94.33,71.5 93.82,72.01 93.82,76.45 94.71,77.34 107.54,77.34 107.79,77.09 116.93,77.09 117.44,76.58 117.44,72.01 116.93,71.5
GND on TOP: 24.22,44.58 30.57,44.58 31.59,45.59 31.59,47.62 31.46,47.75 29.68,47.75 29.18,47.24 28.41,47.24 28.29,47.37 28.29,47.88 28.41,48.01 28.41,48.26 28.29,48.39 28.03,48.39 27.65,48.01 27.27,48.01 26.89,47.62 24.48,47.62 23.84,46.99 23.84,44.96
GND on TOP: 71.21,43.81 71.21,38.99 83.97,38.99 83.97,51.3 78.7,51.3
GND on TOP: 97.63,127.25 97.63,122.68 103.09,117.22 103.09,112.78 102.33,112.01 102.33,103.63 102.96,103 106.52,103 107.41,103.89 107.41,107.31 109.19,109.09 114.9,109.09 115.28,109.47 115.28,110.74 108.17,117.86 107.03,117.86 106.77,118.11 106.77,120.02 107.03,120.27 108.93,120.27 119.35,109.86 119.98,109.86 120.74,110.62 120.74,116.33 118.97,118.11 118.97,122.81 114.52,127.25
GND on TOP: 0.7,0.64 0.7,7.82 11.02,7.82 13.38,5.47 36.71,5.47 36.71,11.12 32.91,14.92 32.91,17.99 37.37,22.45 37.37,27.14 38.78,28.55 38.78,30.04 39.19,30.44 41.64,30.44 42.94,29.14 46.11,29.14 46.74,29.78 46.74,32.56 47.34,33.16 50.65,33.16 50.98,32.82 50.98,18.03 50.5,17.55 47.56,17.55 47.31,17.8 41.42,17.8 41.24,17.62 41.24,11.82 41.95,11.12 46.81,11.12 46.81,4.94 46.8,4.94 46.8,0.64
GND on TOP: 65.88,35.43 58.89,35.43 58.39,35.94 58.39,36.96 58.77,37.34 61.69,37.34 62.2,37.85 62.58,37.85 62.96,38.23 63.21,38.23 63.47,37.97 63.21,37.72 63.21,37.34 63.34,37.21 63.97,37.21 64.36,37.59 65.88,37.59 66.01,37.46 66.01,35.56
GND on TOP: 106.64,0.73 106.64,24.26 120.53,24.26 120.53,22.05 118.97,22.05 118.97,20.22 120.53,20.22 120.53,11.62 121.51,11.62 121.51,1.4 120.84,0.73
GND on TOP: 86.43,98.11 86.43,99.18 88.2,100.95 88.2,101.27 84.36,105.11 74.78,105.11 74.59,105.3 74.59,111.61 74.12,112.08 74.12,115.46 72.48,117.09 70.58,117.09 68.29,119.38 68.29,120.65 68.67,121.03 79.98,121.03 80.23,120.78 80.23,113.67 80.48,113.41 85.06,113.41 85.44,113.03 86.71,113.03 86.96,113.28 87.98,113.28 88.23,113.54 88.23,115.7 87.09,116.84 82.39,116.84 82.39,117.6 82.52,117.73 82.52,120.65 82.77,120.9 87.85,120.9 88.23,120.52 88.23,116.59 90.26,114.55 90.26,113.16 90.77,112.65 95.34,112.65 95.72,112.27 95.72,99.06 94.47,97.8 92.41,97.8 92.4,97.8 86.74,97.8
GND on TOP: 59.17,92.48 59.17,91.82 59.99,91.01 60.27,91.01 60.83,91.57 60.83,91.77 61.33,91.77 63.47,89.64 63.47,89.43 63.87,89.03 64.56,89.03 64.89,89.36 64.89,91.92 64.53,92.28 63.72,92.28 62.48,93.52 60.22,93.52
GND on TOP: 55.97,40.51 66.64,40.51 66.64,46.61 72.36,52.32 72.36,52.83 71.21,53.98 69.69,53.98 64.99,58.67 60.29,58.67 59.91,58.29 59.91,51.69 55.97,47.75
GND on TOP: 14.19,129.03 14.19,121.54 14.57,121.16 15.71,121.16 15.84,121.03 15.84,118.87 16.35,118.36 19.52,118.36 19.91,118.75 19.91,121.28 20.54,121.92 39.84,121.92 39.84,127.25 40.35,127.76 51.66,127.76 51.91,128.02 51.91,128.91 51.78,129.03
GND on TOP: 119.47,67.18 119.73,66.93 121.12,66.93 121.51,66.55 121.51,60.07 121.63,59.94 125.44,59.94 125.82,60.33 125.82,62.36 124.05,64.14 124.05,64.26 123.28,65.02 122.65,65.02 122.52,65.15 122.52,67.06 121.63,67.94 121.63,70.23 121.12,70.74 119.73,70.74 119.47,70.48
GND on TOP: 59.91,2.41 59.91,0.76 97.25,0.76 97.38,0.89 97.38,10.41 96.99,10.79 93.31,10.79 82.26,21.84 78.71,21.84 78.2,21.34 78.2,10.41 76.93,9.14 76.93,7.87 76.17,7.11 74.26,7.11 74.01,7.37 74.01,9.27 72.61,10.67 72.61,14.22 71.34,15.49 71.34,22.1 70.83,22.61 67.78,22.61 67.4,22.99 67.4,28.32 67.02,28.7 58.13,28.7 56.23,26.8 56.23,6.1
GND on BOTTOM: 118.84,55.88 126.33,48.39 128.74,48.39 129,48.64 129,79.88 128.74,80.14 122.52,80.14 121.89,79.5 121.89,67.31 118.84,64.26
GND on BOTTOM: 0.98,96.01 21.94,96.01 22.45,95.5 22.45,90.8 22.95,90.3 26.64,90.3 27.14,90.8 27.14,109.6 26.51,110.24 20.54,110.24 19.78,111 19.78,121.28 20.16,121.67 39.59,121.67 39.97,122.05 39.97,128.91 39.59,129.29 13.43,129.29 12.79,128.65 12.79,122.3 13.81,121.28 15.08,121.28 16.22,120.14 16.22,105.66 15.84,105.28 14.83,105.28 14.32,105.79 14.32,107.57 14.95,108.2 14.95,119 14.7,119.25 11.02,119.25 8.98,121.28 8.98,129.03 8.86,129.16 3.01,129.16 0.98,127.13
GND on BOTTOM: 57.55,49 58.06,49.51 60.38,49.51 71.53,38.36 71.53,33.64 70.86,32.97 61.86,32.97 60.49,31.61 57.76,31.61 57.55,31.82
GND on BOTTOM: 48.62,57.8 48.62,70.14 45.87,72.89 39.85,72.89 37.1,70.14 26.37,59.42 26.37,57.97 26.54,57.8
GND on BOTTOM: 49.66,90.64 50.77,91.74 51.12,91.74 52.07,90.8 52.09,90.76 52.07,90.72 51.47,90.13 51.47,90.11 50.8,89.43 50.31,89.43 49.66,90.08
GND on BOTTOM: 106.64,0.73 106.64,24.26 120.53,24.26 120.53,11.62 121.51,11.62 121.51,1.4 120.87,0.76 120.53,0.76 120.53,0.73
GND on BOTTOM: 20.87,83.4 20.87,80.47 19.14,78.74 19.14,76.83 19.4,76.58 21.81,76.58 22.19,76.58 23.59,77.97 23.59,83.31 23.08,83.82 21.29,83.82
GND on BOTTOM: 70.32,60.96 69.05,60.96 68.8,61.21 68.8,62.1 68.93,62.23 70.07,62.23 70.83,62.99 71.98,62.99 72.23,62.74 72.23,61.98 71.85,61.59 70.96,61.59
GND on BOTTOM: 12.88,85.46 12.88,89.3 13.24,89.66 18.38,89.66 18.51,89.53 18.51,87.76 18.52,87.76 18.77,87.5 18.77,85.07 18.13,84.43 17.3,84.43 17.09,84.64 14.23,84.64 14,84.87 14,85.26 13.91,85.35 12.99,85.35
GND on BOTTOM: 47.5,84.82 47.06,85.27 47.06,88.04 48.01,88.99 48.67,88.99 50.13,87.53 50.13,87.15 47.81,84.82
GND on BOTTOM: 123.16,98.17 123.16,91.31 128.87,91.31 128.87,111.89 125.19,111.89 124.43,112.65 124.43,121.41 123.03,122.81 110.71,122.81 110.08,122.17 110.08,116.97 110.84,116.2 114.52,116.2 116.55,114.17 116.55,111.63 121.38,106.81 121.38,99.95
GND on BOTTOM: 31.08,31.88 38.19,31.88 39.08,32.77 39.08,35.94 37.99,37.03 36.64,37.03 36.13,37.54 33.59,37.54 33.08,37.03 33.08,36.14 32.57,35.63 32.57,34.38 30.95,32.77 30.95,32
GND on BOTTOM: 79.09,99.19 78.71,99.19 77.5,97.98 77.5,97.85 78.58,96.77 78.58,96.66 79.86,95.38 80.1,95.38 81.28,96.55 81.28,96.76 81.07,96.97 81.07,97.21
GND on BOTTOM: 48.4,83.93 48.38,83.97 48.4,84 49.01,84.62 49.05,84.63 49.08,84.62 49.85,83.85 50.34,83.85 50.79,83.39 50.79,83.26 50.63,83.1 50.62,83.07 50.01,82.47 50.01,82.46 49.94,82.43 49.86,82.46
GND on BOTTOM: 52.32,81.36 52.14,81.19 51.54,81.19 51.05,81.68 51.05,81.96 51.39,82.3 51.43,82.31 51.47,82.3 51.65,82.3 52.32,81.64
GND on BOTTOM: 81.12,36.7 81.12,69.09 86.07,69.09 89.12,66.04 98.14,66.04 98.65,65.53 98.65,61.59 98.39,61.34 94.96,61.34 94.58,60.96 94.58,59.05 94.2,58.67 92.55,58.67 91.53,57.66 91.53,51.05 90.39,49.91 86.71,49.91 86.07,49.28 86.07,46.1 87.22,44.96 90.01,44.96 90.52,45.47 90.52,48.13 91.53,49.15 102.84,49.15 103.6,48.39 103.6,44.83 103.09,44.32 98.26,44.32 97.63,43.69 97.63,40.01 97.25,39.62 96.11,39.62 95.98,39.5 95.98,37.97 94.71,36.7
GND on BOTTOM: 0.98,0.64 0.98,12.32 3.01,12.32 6.57,15.88 11.02,15.88 12.67,17.53 12.67,22.86 16.98,27.18 25.11,27.18 28.03,24.26 36.03,24.26 37.75,22.54 37.75,11.24 38.96,10.03 40.73,10.03 42,8.76 42,6.35 42.38,5.97 43.02,5.97 43.91,5.08 62.2,5.08 62.96,5.84 62.96,24.51 63.59,25.15 77.69,25.15 81.37,28.83 81.37,33.66 81.75,34.04 94.58,34.04 96.36,32.26 96.36,12.57 97.25,11.68 100.8,11.68 101.69,10.79 101.69,1.02 101.31,0.64 ; 1 cut-out
GND on BOTTOM: 73.65,39.46 74.76,39.46 75.04,39.74 75.04,64.01 74.88,64.17 73.91,64.17 73.59,63.85 73.59,62.74 73.83,62.5 73.83,61.85 73.28,61.3 72.78,61.3 72.62,61.13 72.62,61.01 72.83,60.79 72.83,60.05 72.52,59.74 72.52,56.9 71.9,56.28 71.9,55.62 70.01,53.73 69.42,53.73 66.3,56.85 66.3,56.88 66,56.88 65.37,56.25 64.96,56.25 64.23,56.98 64.23,57.84 66.4,60.01 66.4,63.47 66.07,63.81 64.62,63.81 59.29,58.47 59.29,56.14 64.04,51.39 64.04,49.07
GND on BOTTOM: 25.61,77.06 25.92,77.06 27.59,75.38 27.59,72.86 23.76,69.03 23.76,67.88 24.8,66.84 25.81,66.84 35.05,76.08 35.05,82.15 34.48,82.73 26.13,82.73 25.61,82.21
GND on L2_GND_1, L7_GND_2: 129.34,0.66 0.66,0.66 0.66,129.34 129.34,129.34
GND on L3_INT_1: 111.35,49.66 108.93,52.07 108.93,54.36 111.47,56.9 111.47,65.66 110.2,66.93 109.44,66.93 102.58,60.07 91.39,60.07 80.61,70.86 80.61,73.63 88.13,81.15 115.03,81.15 120.62,86.74 120.62,94.23 121.25,94.87 122.14,94.87 124.05,92.96 124.05,57.28 116.43,49.66
GND on L3_INT_1: 14.83,71.88 14.83,67.94 13.17,66.29 13.17,56.64 13.68,56.13 15.33,56.13 20.16,60.96 20.16,67.44 28.8,76.07 28.8,76.58 27.53,77.85 27.14,77.85 22.45,73.15 16.1,73.15
GND on L3_INT_1: 1.11,1.14 1.11,13.72 2.63,15.24 16.35,15.24 24.1,22.99 52.29,22.99 55.08,25.78 58.89,25.78 60.16,24.51 60.16,17.4 59.28,16.51 55.72,16.51 55.21,16 55.21,14.86 55.59,14.48 62.45,14.48 63.34,15.37 63.34,28.83 52.42,39.75 52.42,57.02 52.67,57.28 54.2,57.28 77.06,34.42 77.06,24 88.1,12.95 94.07,12.95 95.09,11.94 95.09,1.14
GND on L3_INT_1: 40.5,41.58 40.5,39.56 39.32,38.38 39.32,31.32 35.67,27.66 32.51,27.66 31.77,26.92 31.77,26.29 32.02,26.04 48.18,26.04 48.18,41.58
GND on L3_INT_1: 115.54,96.77 115.54,108.33 118.08,108.33 125.44,115.7 125.44,122.05 124.43,123.06 124.43,127.76 124.81,128.14 128.36,128.14 129.36,127.14 129.36,43.04 128.87,42.55 118.58,42.55 117.31,43.81 117.31,48.39 125.19,56.26 125.19,94.61 123.03,96.77
GND on L3_INT_1: 97.17,0.73 97.17,11.85 102.4,11.85 102.4,22.21 99.99,22.21 99.99,22.82 97.82,22.82 97.82,29.17 129.32,29.17 129.32,0.73
GND on L4_PWR_1: 106.64,0.73 106.64,21.89 107.67,22.93 121.25,22.93 121.25,19.68 129.14,19.68 129.14,0.73
GND on L5_PWR_2: 129.29,29.12 129.29,0.75 97.94,0.75 97.94,25.44 105.07,25.44 105.07,29.12
GND on L6_INT_2: 36.59,55.47 36.59,57.31 37.57,58.29 37.57,66.32 37.25,66.64 28.25,66.64 23.57,61.95 23.57,56.59 24.39,55.77 24.39,54.5 26.63,52.26 29.82,52.26 30,52.44 30,54.69 30.77,55.47
GND on L6_INT_2: 101.31,77.34 101.31,67.44 107.79,67.44 107.79,82.42 106.27,82.42 106.01,82.68 91.79,82.68 88.61,79.5 88.61,78.36 89.5,77.47 101.19,77.47
GND on L6_INT_2: 0.73,51.05 9.36,51.05 9.36,51.18 12.41,54.23 15.08,54.23 18.51,57.66 18.51,62.87 27.02,71.37 27.02,73.66 26,74.68 9.36,74.68 4.79,79.25 4.79,95.25 13.43,103.89 33.75,103.89 34.13,104.27 34.13,114.17 43.02,123.06 71.53,123.06 72.92,121.67 79.98,121.67 83.53,118.11 83.53,109.73 84.42,108.84 93.57,108.84 94.45,109.73 94.45,122.05 95.47,123.06 127.6,123.06 128.87,124.33 128.87,127.64 127.47,129.03 1.87,129.03 0.73,127.89
GND on L6_INT_2: 119.23,65.28 119.23,81.65 115.54,85.34 110.2,85.34 109.82,84.96 109.82,67.06 109.31,66.55 109.31,55.63 111.98,52.96 111.98,41.15 111.09,40.26 111.09,32.77 111.35,32.51 114.14,32.51 117.44,35.81 117.44,48.01 119.23,49.8 119.23,49.91 120.11,50.79 120.11,64.4
GND on L6_INT_2: 32.06,25.94 31.6,26.41 31.6,27.55 32.08,28.03 41.41,28.03 41.41,47.65 50.41,47.65 53.78,51.01 53.78,51.01 58.51,55.75 58.51,67.06 59.15,67.69 77.18,67.69 77.18,63.37 65.75,63.37 65.12,62.74 65.12,56.77 65.88,56.01 83.28,56.01 84.8,54.48 84.8,52.45 84.17,51.82 63.34,51.82 63.09,51.56 63.09,51.01 63.29,51.01 63.87,50.44 84.69,50.44 84.69,38.43 64.3,38.43 62.81,36.94 62.81,25.94
GND on L6_INT_2: 29.28,80.33 29.28,67.44 29.42,67.29 39.37,67.29 43.77,71.68 43.77,80.33
GND on L6_INT_2: 86.52,93.51 86.52,95.91 85.69,95.91 82.84,98.76 82.39,98.76 81.74,99.41 78.13,99.41 77.61,98.9 74.93,98.9 73.61,100.22 66.9,100.22 66.12,99.44 66.12,94.48 67.09,93.51
GND on L6_INT_2: 16.45,83.62 12.74,83.62 12.2,84.15 10.48,84.15 10.37,84.26 10.37,88.63 10.57,88.83 18.93,88.83 19.06,88.7 19.06,86.23
GND on L6_INT_2: 5.44,39.92 5.44,28.53 14.23,28.53 15.58,27.18 22.8,27.18 26.17,23.81 32.05,23.81 32.05,25.22 28.43,28.84 28.43,29.83 27.86,30.4 27.86,39.92
GND on L6_INT_2: 1.36,9.02 1.36,0.76 96.11,0.76 96.36,1.02 96.36,28.19 94.96,29.59 84.04,29.59 82.39,31.24 72.48,31.24 64.23,22.99 25.11,22.99 22.06,26.04 14.57,26.04 10.51,21.97 10.51,20.95 11.4,20.07 11.9,20.07 12.41,19.56 12.41,18.8 11.9,18.29 10.63,18.29
GND on L6_INT_2: 106.64,0.75 106.64,9.69 115.02,9.69 115.02,10.41 106.64,10.41 106.64,24.85 128.43,24.85 128.43,0.75
GND on L6_INT_2: 88.65,96.37 87.88,97.14 87.88,98.31 85.85,100.33 75.54,100.33 75.05,100.82 75.05,101.82 76.19,102.96 87.39,102.96 87.39,102.76 90.62,99.53 98.5,99.53 98.5,96.37
GND on L6_INT_2: 124.3,93.47 124.3,53.85 123.03,52.58 123.03,49.66 118.84,45.47 118.84,34.92 115.92,32 115.92,31.24 116.43,30.73 129.25,30.73 129.25,93.47
VCCI_EMMC on BOTTOM: 67.66,62.74 70.07,62.74 70.71,63.37 71.85,63.37 72.1,63.63 72.1,64.77 71.85,65.02 67.78,65.02 67.4,64.64 67.4,62.99
VDD_1P2_CAP on L3_INT_1: 58.26,83.57 58.45,83.38 59.85,83.38 60.96,83.38 61.38,83.8 62.21,83.8 62.63,83.38 64.67,83.38 65.02,83.72 65.02,86.33 64.86,86.49 60.93,86.49 59.38,84.94 58.31,84.94 58.26,84.89
VDD_1V8 on TOP: 16.73,67.94 11.14,67.94 9.11,69.98 9.11,74.17 10.25,75.31 14.32,75.31 14.57,75.06 14.57,74.04 15.21,73.41 16.6,73.41 17.11,72.9 17.11,68.33
VDD_1V8 on BOTTOM: 45.94,28.32 45.81,28.45 45.81,30.73 49.12,34.04 49.12,45.85 46.07,48.89 27.91,48.89 24.86,51.94 24.86,56.39 25.24,56.77 53.05,56.77 56.99,52.83 56.99,30.99 54.32,28.32
VDD_1V8 on BOTTOM: 121.76,8.64 121.76,10.92 122.27,11.43 122.27,16.89 123.54,18.16 123.54,26.92 121.63,28.83 121.63,39.5 116.3,44.83 114.52,44.83 114.14,45.21 114.14,49.28 114.52,49.66 124.05,49.66 125.95,47.75 125.95,33.27 127.6,31.62 127.6,8.64
VDD_1V8 on BOTTOM: 80.42,83.6 80.42,81.68 80.13,81.38 80.13,80.8 80.28,80.64 82.05,80.64 82.53,81.13 82.53,81.15 82.64,81.26 82.64,82.8 82.96,83.12 83.13,83.12 83.49,83.48 83.49,84.25 83.42,84.32 81.51,84.32 80.95,83.76 80.58,83.76
VDD_1V8 on BOTTOM: 82.9,92.71 82.64,92.46 80.87,92.46 80.48,92.84 80.48,94.61 80.61,94.74 82.77,94.74 82.9,94.61
VDD_1V8 on L3_INT_1: 3.9,37.08 7.33,37.08 8.09,37.85 8.09,41.91 13.17,46.99 13.17,50.29 11.78,51.69 11.78,74.17 11.27,74.68 8.35,74.68 7.59,73.91 7.59,52.2 8.98,50.8 8.98,47.12 3.78,41.91 3.78,37.21
VDD_1V8 on L4_PWR_1: 61.18,83.03 61.18,82.32 62.31,81.18 62.31,80.41 62.62,80.1 62.62,80.04 62.73,79.93 63.73,79.93 63.97,80.17 64.66,80.17 64.91,80.42 67.08,80.42 67.28,80.62 78.07,80.62 80.41,78.29 80.67,78.03 81.25,77.44 81.25,77.44 81.43,77.26 81.43,75.26 81.62,75.07 86.15,75.07 86.72,74.5 86.72,58.18 88.99,55.91 88.99,47.24 89.25,46.99 101.44,46.99 103.6,44.83 115.79,44.83 115.79,58.2 115.48,58.51 113.34,58.51 112.76,59.09 112.76,67.51 112.49,67.79 92.21,67.79 91.52,68.49 91.52,83.01 91.22,83.31 79.02,83.31 79.02,83.31 64.91,83.31 64.8,83.2 63.9,82.3 63.12,82.3 62.87,82.55 62.87,83.16 62.67,83.36 61.51,83.36
VDD_1V8 on L5_PWR_2: 73.95,79.61 79.64,85.3 79.64,87.38 78.26,88.75 71.6,88.75 69.94,87.1 68,87.1 67.79,87.3 67.79,88.4 67.85,88.46 67.85,89.89 66.89,90.86 66.89,91.18 77.01,101.3 77.01,108.3 77.17,108.45 79.36,108.45 80.21,109.3 80.21,111.37 70.22,121.36 51.25,121.36 47.52,117.63 47.52,97.34 46.96,96.77 33.49,96.77 31.55,94.82 31.55,80.05 32.99,78.61 32.99,62.99 29.68,59.69 29.68,44.32 29.43,44.07 11.4,44.07 10.89,44.58 10.89,56.07 12.13,57.31 12.13,65.99 10.89,67.23 10.89,80.39 11.52,81.03 21.62,81.03 22.85,82.25 22.85,115.57 27.81,115.57 31.74,119.5 31.74,127.41 94.15,127.41 95.96,125.59 95.96,77.69 95.53,77.26 92.56,77.26 91.91,76.62 91.91,72.52 77.69,72.52 73.95,76.26
VDD_1V8_L3 on TOP: 13.52,83.28 12.16,81.92 12.16,80.9 12.29,80.77 14.44,80.77 14.55,80.87 14.55,82.4 14.78,82.63 14.78,84.32 14.58,84.32 14.58,83.49 14.36,83.28
VDD_1V8_SNS on TOP: 14.44,80.14 9.59,80.14 9.53,80.08 9.53,75.98 9.69,75.82 14.32,75.82 14.57,76.07 14.57,80.01
VDD_1V8_SNS on L6_INT_2: 14.79,78.93 11.08,78.93 10.62,79.38 10.62,80.25 10.76,80.39 13.32,80.39 19.59,86.67 21.44,86.67 21.6,86.51 21.6,85.71 21.45,85.57 20.92,85.57 18.57,83.21 18.57,82.71
